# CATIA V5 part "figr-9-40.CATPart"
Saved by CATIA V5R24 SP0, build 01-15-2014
Part number: Part1
Bounding box of the stored display mesh (mm): x -40 to 40, y -20 to 191.034, z 0 to 131.919
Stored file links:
  D:\KAVITA\CATIA V5-6R2014 Project_ Kavita\CATIA V5-6R2014_partfiles\Partfiles\c09_catia_v5-6r2014_prt\figr-9-40.CATPart
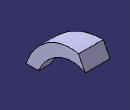
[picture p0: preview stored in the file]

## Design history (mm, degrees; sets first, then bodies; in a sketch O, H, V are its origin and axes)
Set1
  Plane1: type Normal, Curve Sketch2, RefPoint vertex of Sketch2
Body1 (main body)
  Sketch1 on xy-plane, origin (0, 0, 0), H (1, 0, 0), V (0, 1, 0)
    line L1 (20, 20) -> (20, -20)
    line L2 (20, -20) -> (-20, -20)
    line L3 (-20, -20) -> (-20, 20)
    line L4 (-20, 20) -> (20, 20)
    vertical: L1 V, L3 V
    horizontal: L2 H, L4 H
    equidistance: L1 L3 O, L2 L4 O
  Sketch2 on yz-plane, origin (0, 0, 0), H (0, 1, 0), V (0, 0, 1)
    spline S1 through (0, 0) (20, 60) (60, 80) (120, 90) (180, 110)
    point P1 (0, 0)
    coincidence: P1 O
  Sketch3 on Plane1, origin (0, 186.3865, 97.8327), H (1, 0, 0), V (0, -0.4648, 0.8854)
    point P1 (0, 13.7415)
    line L1 (40, 37.4831) -> (40, -10)
    line L2 (40, -10) -> (-40, -10)
    line L3 (-40, -10) -> (-40, 37.4831)
    line L4 (-40, 37.4831) -> (40, 37.4831)
    reference projected point E1 (0, 13.7415) from vertex of Sketch2
    coincidence: P1 V, P1 E1
    vertical: L1 V, L3 V
    horizontal: L2 H, L4 H
    equidistance: L1 L3 P1, L2 L4 P1
  Loft1: Sections (Sketch1; Sketch3)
